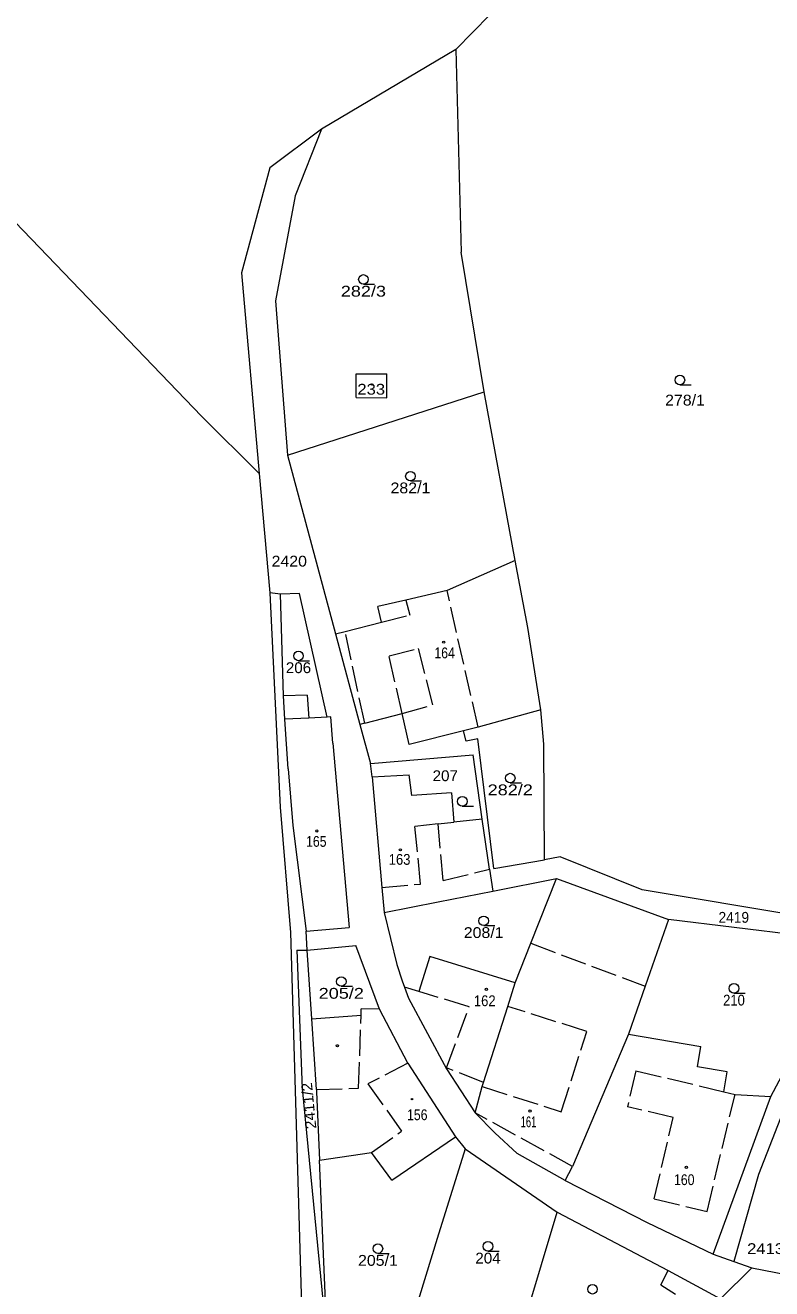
# Model space of a CAD drawing. Extents: x -590528 to -586543, y -1119609 to -1116685.
# Drawn here: x -589035.6 to -588918.2, y -1118121.8 to -1117923.1 of the extents above; entities that cross this region are included whole.
import ezdxf
from ezdxf.enums import TextEntityAlignment as Align

# ---------------------------------------------------------------- set-up
doc = ezdxf.new("R2010")
doc.units = 0
doc.header["$LTSCALE"] = 0.68
doc.linetypes.add('LONG_DASHED', pattern=[7.5, 6, -1.5])
for name, color, linetype, lineweight in [('1', 7, 'Continuous', 13), ('2', 7, 'LONG_DASHED', 13), ('3', 7, 'Continuous', 13), ('6', 7, 'Continuous', 13)]:
    doc.layers.add(name, color=color, linetype=linetype, lineweight=lineweight)

msp = doc.modelspace()

# ---------------------------------------------------------------- linework, layer by layer
at = {"layer": '1'}
for p, q in [((-588967.92, -1117926.89), (-588957.66, -1117916.42)), ((-588967.92, -1117926.89), (-588967.07, -1117958.77)), ((-589037.19, -1117954.07), (-589007.92, -1117984.57)), ((-588996.25, -1117966.42), (-588994.37, -1117990.7)), ((-588983.59, -1117981.63), (-588983.56, -1117977.89)), ((-588983.56, -1117977.89), (-588978.75, -1117977.93)), ((-588978.78, -1117981.67), (-588978.75, -1117977.93)), ((-588994.37, -1117990.7), (-588963.43, -1117980.72)), ((-588983.59, -1117981.63), (-588978.78, -1117981.67)), ((-589007.92, -1117984.57), (-588998.82, -1117993.6)), ((-588994.37, -1117990.7), (-588986.82, -1118018.81)), ((-588958.58, -1118007.24), (-588969.29, -1118012)), ((-588956.59, -1118017.78), (-588958.58, -1118007.24)), ((-588997.17, -1118012.33), (-588995.54, -1118046.08)), ((-588992.51, -1118012.43), (-588995.46, -1118012.57)), ((-588988.14, -1118031.89), (-588992.51, -1118012.43)), ((-588979.6, -1118016.98), (-588980.17, -1118014.48)), ((-588954.52, -1118030.75), (-588956.59, -1118017.78)), ((-588991.26, -1118028.42), (-588995.01, -1118028.57)), ((-588991.26, -1118028.42), (-588991.03, -1118032.04)), ((-588987.23, -1118035.97), (-588987.55, -1118031.86)), ((-588982.23, -1118032.87), (-588976.34, -1118031.3)), ((-588975.23, -1118036.2), (-588976.34, -1118031.3)), ((-588954.52, -1118030.75), (-588964.4, -1118033.49)), ((-588954.07, -1118036.17), (-588954.52, -1118030.75)), ((-588982.23, -1118032.87), (-588982.99, -1118033.07)), ((-588966.28, -1118035.67), (-588966.72, -1118034.07)), ((-588987.23, -1118035.97), (-588986.14, -1118048.4)), ((-588964.43, -1118035.32), (-588966.28, -1118035.67)), ((-588961.93, -1118055.71), (-588964.43, -1118035.32)), ((-588981.34, -1118039.19), (-588965.19, -1118037.82)), ((-588963.75, -1118047.92), (-588965.19, -1118037.82)), ((-588994.25, -1118040), (-588993.54, -1118048.93)), ((-588981.04, -1118041.29), (-588981.34, -1118039.19)), ((-588981.04, -1118041.29), (-588975.25, -1118040.95)), ((-588981.04, -1118041.29), (-588979.54, -1118058.68)), ((-588974.82, -1118044.22), (-588975.25, -1118040.95)), ((-588968.59, -1118043.8), (-588974.82, -1118044.22)), ((-588968.59, -1118043.8), (-588968.21, -1118048.39)), ((-588995.54, -1118046.08), (-588993.92, -1118065.79)), ((-588963.75, -1118047.92), (-588968.21, -1118048.39)), ((-588962.62, -1118055.82), (-588963.75, -1118047.92)), ((-588993.54, -1118048.93), (-588991.45, -1118065.54)), ((-588986.14, -1118048.4), (-588984.69, -1118064.99)), ((-588938.59, -1118059.07), (-588951.52, -1118053.84)), ((-588962.62, -1118055.82), (-588962.07, -1118059.26)), ((-588961.93, -1118055.71), (-588953.97, -1118054.32)), ((-588952.08, -1118057.29), (-588934.47, -1118063.73)), ((-588979.54, -1118058.68), (-588979.16, -1118062.64)), ((-588909.17, -1118063.97), (-588938.59, -1118059.07)), ((-588905.49, -1118067.28), (-588934.47, -1118063.73)), ((-588993.92, -1118065.79), (-588991.42, -1118150.69)), ((-588991.45, -1118065.54), (-588984.69, -1118064.99)), ((-588991.26, -1118068.53), (-588983.61, -1118067.82)), ((-588979.89, -1118077.83), (-588983.61, -1118067.82)), ((-588992.89, -1118068.53), (-588992.07, -1118090.31)), ((-588990.56, -1118079.33), (-588991.26, -1118068.53)), ((-588982.81, -1118078.77), (-588982.78, -1118077.78)), ((-588990.56, -1118079.33), (-588982.81, -1118078.77)), ((-588989.84, -1118090.46), (-588990.56, -1118079.33)), ((-588940.77, -1118081.74), (-588949.56, -1118102.54)), ((-588940.77, -1118081.74), (-588929.39, -1118083.71)), ((-588929.92, -1118086.88), (-588929.39, -1118083.71)), ((-588925.25, -1118087.66), (-588929.92, -1118086.88)), ((-588925.77, -1118090.8), (-588925.25, -1118087.66)), ((-588963.77, -1118089.99), (-588963.56, -1118089.35)), ((-588977.96, -1118104.72), (-588967.95, -1118097.88)), ((-588989.35, -1118101.59), (-588981.16, -1118100.37)), ((-588977.96, -1118104.72), (-588981.16, -1118100.37)), ((-588966.42, -1118099.78), (-588970.83, -1118113.91)), ((-588966.42, -1118099.78), (-588951.97, -1118109.75)), ((-588950.69, -1118104.75), (-588958.24, -1118100.5)), ((-588950.69, -1118104.75), (-588949.56, -1118102.54)), ((-588950.69, -1118104.75), (-588937.84, -1118111.37)), ((-588920.34, -1118103.8), (-588924.17, -1118117.5)), ((-588958.38, -1118131.22), (-588951.97, -1118109.75)), ((-588951.97, -1118109.75), (-588934.5, -1118118.92)), ((-588970.83, -1118113.91), (-588976.15, -1118131.23)), ((-588935.65, -1118121.17), (-588934.5, -1118118.92)), ((-588934.5, -1118118.92), (-588926.3, -1118123.37)), ((-588921.38, -1118118.49), (-588926.3, -1118123.37)), ((-588921.38, -1118118.49), (-588901.98, -1118122.35)), ((-588935.65, -1118121.17), (-588933.39, -1118122.65))]:
    msp.add_line(p, q, dxfattribs=at)
for points in [[(-588967.92, -1117926.89), (-588989.04, -1117939.45), (-588993.16, -1117949.93), (-588996.25, -1117966.42)], [(-588989.04, -1117939.45), (-588997.14, -1117945.51), (-589001.61, -1117962.03)], [(-588958.58, -1118007.24), (-588963.43, -1117980.72), (-588967.07, -1117958.77)], [(-589001.61, -1117962.03), (-588998.82, -1117993.6), (-588997.17, -1118012.33)], [(-588969.29, -1118012), (-588975.76, -1118013.48), (-588980.17, -1118014.48)], [(-588995.01, -1118028.57), (-588995.46, -1118012.57), (-588997.17, -1118012.33)], [(-588986.82, -1118018.81), (-588985.33, -1118018.43), (-588979.6, -1118016.98)], [(-588986.82, -1118018.81), (-588982.99, -1118033.07), (-588981.34, -1118039.19)], [(-588994.25, -1118040), (-588994.77, -1118032.23), (-588995.01, -1118028.57)], [(-588987.55, -1118031.86), (-588988.14, -1118031.89), (-588991.03, -1118032.04)], [(-588964.4, -1118033.49), (-588966.72, -1118034.07), (-588975.23, -1118036.2)], [(-588951.52, -1118053.84), (-588953.97, -1118054.32), (-588954.07, -1118036.17)], [(-588979.16, -1118062.64), (-588970.69, -1118060.96), (-588962.07, -1118059.26), (-588952.08, -1118057.29)], [(-588958.56, -1118073.69), (-588956.1, -1118067.46), (-588952.08, -1118057.29)], [(-588979.16, -1118062.64), (-588977.18, -1118070.79), (-588976.35, -1118073.38), (-588975.98, -1118074.36), (-588975.33, -1118076.1), (-588969.39, -1118087.2)], [(-588934.47, -1118063.73), (-588938.14, -1118074.21), (-588940.77, -1118081.74)], [(-588992.89, -1118068.53), (-588991.26, -1118068.53), (-588991.45, -1118065.54)], [(-588918.36, -1118091.58), (-588910.42, -1118076.58), (-588905.49, -1118067.28)], [(-588958.56, -1118073.69), (-588972, -1118069.52), (-588973.71, -1118075.02), (-588975.98, -1118074.36)], [(-588963.56, -1118089.35), (-588959.74, -1118077.38), (-588958.56, -1118073.69)], [(-588975.43, -1118086.32), (-588979.89, -1118077.83), (-588982.78, -1118077.78)], [(-588909.4, -1118081.92), (-588916.04, -1118092.82), (-588920.34, -1118103.8)], [(-588975.43, -1118086.32), (-588967.95, -1118097.88), (-588966.42, -1118099.78)], [(-588969.39, -1118087.2), (-588964.87, -1118094.14), (-588963.77, -1118089.99)], [(-588992.07, -1118090.31), (-588988.11, -1118131.1), (-588989.35, -1118101.59)], [(-588989.84, -1118090.46), (-588989.82, -1118090.82), (-588989.35, -1118101.59)], [(-588937.84, -1118111.37), (-588927.46, -1118116.34), (-588918.36, -1118091.58)], [(-588925.77, -1118090.8), (-588924.01, -1118091.22), (-588918.36, -1118091.58)], [(-588964.87, -1118094.14), (-588961.76, -1118097.26), (-588958.24, -1118100.5)], [(-588927.46, -1118116.34), (-588924.17, -1118117.5), (-588921.38, -1118118.49)]]:
    msp.add_lwpolyline(points, dxfattribs=at)
at = {"layer": '2'}
for p, q in [((-588964.4, -1118033.49), (-588969.29, -1118012)), ((-588975.76, -1118013.48), (-588975.16, -1118015.86)), ((-588979.6, -1118016.98), (-588975.16, -1118015.86)), ((-588982.23, -1118032.87), (-588985.33, -1118018.43)), ((-588973.84, -1118021.08), (-588971.58, -1118030.02)), ((-588976.34, -1118031.3), (-588971.58, -1118030.02)), ((-588991.03, -1118032.04), (-588994.77, -1118032.23)), ((-588970.7, -1118048.69), (-588974.35, -1118049.08)), ((-588973.45, -1118058.14), (-588974.35, -1118049.08)), ((-588969.91, -1118057.58), (-588962.62, -1118055.82)), ((-588979.54, -1118058.68), (-588973.45, -1118058.14)), ((-588956.1, -1118067.46), (-588938.14, -1118074.21)), ((-588965.81, -1118077.48), (-588973.71, -1118075.02)), ((-588969.35, -1118087.07), (-588965.81, -1118077.48)), ((-588947.31, -1118081.34), (-588959.74, -1118077.38)), ((-588983.2, -1118090.25), (-588982.81, -1118078.77)), ((-588951.34, -1118093.96), (-588947.31, -1118081.34)), ((-588975.43, -1118086.32), (-588981.73, -1118089.55)), ((-588963.56, -1118089.35), (-588969.35, -1118087.07)), ((-588939.58, -1118087.52), (-588940.92, -1118093.16)), ((-588939.58, -1118087.52), (-588925.77, -1118090.8)), ((-588981.73, -1118089.55), (-588976.43, -1118097.01)), ((-588989.84, -1118090.46), (-588983.2, -1118090.25)), ((-588963.77, -1118089.99), (-588951.34, -1118093.96)), ((-588928.4, -1118109.63), (-588924.01, -1118091.22)), ((-588933.72, -1118094.87), (-588940.92, -1118093.16)), ((-588949.56, -1118102.54), (-588964.87, -1118094.14)), ((-588936.71, -1118107.67), (-588933.72, -1118094.87)), ((-588981.16, -1118100.37), (-588976.43, -1118097.01)), ((-588936.71, -1118107.67), (-588928.4, -1118109.63))]:
    msp.add_line(p, q, dxfattribs=at)
for points in [[(-588976.34, -1118031.3), (-588978.41, -1118022.23), (-588973.84, -1118021.08)], [(-588969.91, -1118057.58), (-588970.7, -1118048.69), (-588968.21, -1118048.39)]]:
    msp.add_lwpolyline(points, dxfattribs=at)
at = {"layer": '6'}
for p, q in [((-588982.44, -1117963.81), (-588980.69, -1117963.81)), ((-588932.67, -1117979.63), (-588930.92, -1117979.63)), ((-588975.05, -1117994.75), (-588973.3, -1117994.75)), ((-588992.65, -1118023.02), (-588990.9, -1118023.02)), ((-588959.35, -1118042.23), (-588957.6, -1118042.23)), ((-588966.89, -1118045.89), (-588965.14, -1118045.89)), ((-588963.53, -1118064.68), (-588961.78, -1118064.68)), ((-588985.92, -1118074.23), (-588984.17, -1118074.23)), ((-588924.17, -1118075.3), (-588922.42, -1118075.3)), ((-588980.16, -1118116.23), (-588978.41, -1118116.23)), ((-588962.85, -1118115.87), (-588961.1, -1118115.87))]:
    msp.add_line(p, q, dxfattribs=at)
for centre, radius in [((-588982.44, -1117963.06), 0.75), ((-588932.67, -1117978.88), 0.75), ((-588981.0801, -1117979.5802), 0.1172), ((-588975.05, -1117994), 0.75), ((-588969.8202, -1118020.1004), 0.175), ((-588992.65, -1118022.27), 0.75), ((-588959.35, -1118041.48), 0.75), ((-588966.89, -1118045.14), 0.75), ((-588989.7702, -1118049.7904), 0.175), ((-588976.6202, -1118052.7704), 0.175), ((-588963.53, -1118063.93), 0.75), ((-588985.92, -1118073.48), 0.75), ((-588924.17, -1118074.55), 0.75), ((-588963.1002, -1118074.7104), 0.175), ((-588986.5402, -1118083.5804), 0.175), ((-588974.8001, -1118091.9702), 0.1172), ((-588956.2302, -1118093.8404), 0.175), ((-588931.6502, -1118102.6804), 0.175), ((-588980.16, -1118115.48), 0.75), ((-588962.85, -1118115.12), 0.75), ((-588946.42, -1118121.87), 0.75)]:
    msp.add_circle(centre, radius, dxfattribs=at)

# ---------------------------------------------------------------- texts
at = {"layer": '3'}
for s, width, p in [('282/3', 1.25, (-588982.44, -1117965.76)), ('233', 1.15, (-588981.2115, -1117981.18)), ('278/1', 1.1, (-588931.87, -1117982.89)), ('282/1', 1.1, (-588975.05, -1117996.7)), ('2420', 1.1, (-588994.1, -1118008.22)), ('164', 0.85, (-588969.67, -1118022.64)), ('206', 1.05, (-588992.6505, -1118024.97)), ('207', 1.05, (-588969.57, -1118041.96)), ('282/2', 1.25, (-588959.3505, -1118044.18)), ('165', 0.85, (-588989.8505, -1118052.29)), ('163', 0.9, (-588976.75, -1118055.12)), ('2419', 0.95, (-588924.2, -1118064.23)), ('208/1', 1.1, (-588963.53, -1118066.63)), ('205/2', 1.25, (-588985.92, -1118076.18)), ('162', 0.9, (-588963.3605, -1118077.35)), ('210', 0.9, (-588924.1705, -1118077.25)), ('156', 0.85, (-588973.9705, -1118095.28)), ('161', 0.65, (-588956.48, -1118096.39)), ('160', 0.85, (-588931.9905, -1118105.49)), ('2413/2', 1.15, (-588918.1105, -1118116.33)), ('205/1', 1.1, (-588980.16, -1118118.18)), ('204', 1.05, (-588962.8505, -1118117.82))]:
    msp.add_text(s, height=1.7, dxfattribs=dict(at, width=width)).set_placement(p, align=Align.CENTER)
at = {"layer": '3', "width": 1.05}
msp.add_text('2411/2', height=1.7, rotation=95.627, dxfattribs=at).set_placement((-588990.1886, -1118092.9373), align=Align.CENTER)

doc.saveas('drawing.dxf')
